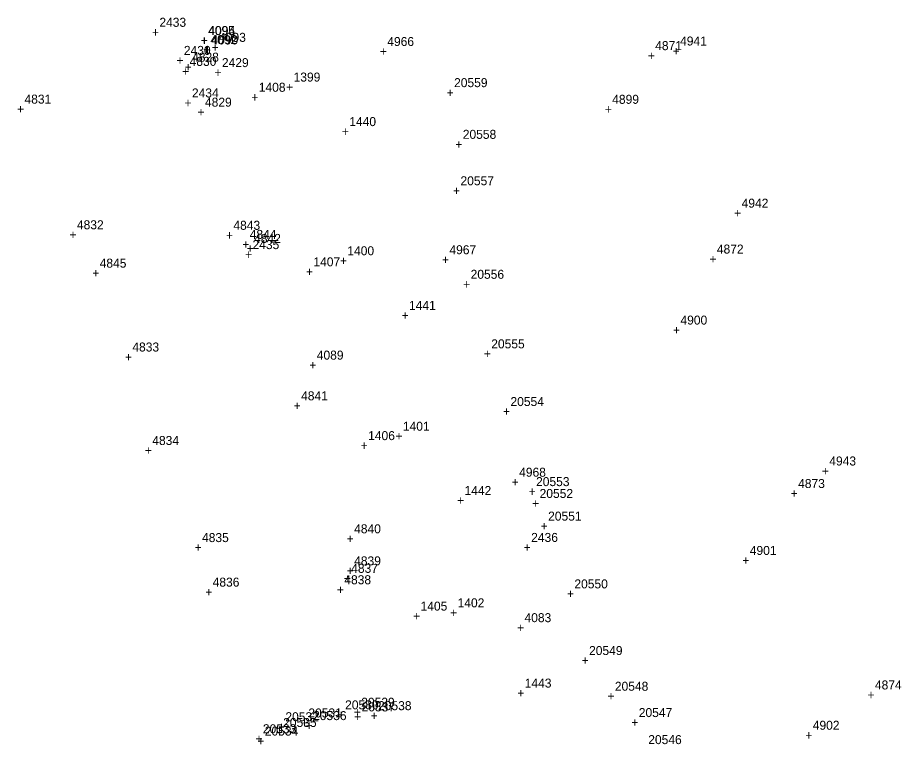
# Model space of a CAD drawing. Extents: x 1036751 to 1042192, y 772604 to 785439.
# Drawn here: x 1038276.6 to 1038522.1, y 779180.8 to 779382.7 of the extents above; entities that cross this region are included whole.
import ezdxf

# ---------------------------------------------------------------- set-up
doc = ezdxf.new("R2010")
doc.units = 0
for name, color, linetype in [('S_Drainage_Ditch_Line', 7, 'Continuous'), ('S_Ground_Elevation', 7, 'Continuous'), ('S_Misc_MiscFeature', 7, 'Continuous'), ('S_Property_IronPipeFound', 7, 'Continuous'), ('S_Property_Mailbox', 7, 'Continuous'), ('S_Property_StoneWall', 7, 'Continuous'), ('S_Roadway_Centerline', 7, 'Continuous'), ('S_Roadway_Edge_Pavement', 7, 'Continuous'), ('S_Trees_Conifer_Pay', 7, 'Continuous'), ('S_Utilities_Pole_Power', 7, 'Continuous'), ('S_Utilities_UG_Water_Gate', 7, 'Continuous'), ('S_Utilities_UG_Water_Line', 7, 'Continuous')]:
    doc.layers.add(name, color=color, linetype=linetype)

msp = doc.modelspace()

# ---------------------------------------------------------------- texts
at = {"layer": 'S_Drainage_Ditch_Line'}
for s, p in [('4871', (1038453.71, 779373.65)), ('+', (1038451.65, 779370.9)), ('4872', (1038470.85, 779317.13)), ('+', (1038468.79, 779314.38)), ('4873', (1038493.43, 779251.98)), ('+', (1038491.37, 779249.23)), ('4874', (1038514.77, 779196.01)), ('+', (1038512.71, 779193.26))]:
    msp.add_text(s, height=2.5, dxfattribs=at).set_placement(p)
at = {"layer": 'S_Ground_Elevation'}
for s, p in [('4966', (1038379.27, 779374.8)), ('4941', (1038460.63, 779374.94)), ('+', (1038377.21, 779372.05)), ('+', (1038458.56, 779372.19)), ('4828', (1038325.04, 779370.45)), ('+', (1038322.97, 779367.7)), ('4899', (1038441.77, 779358.74)), ('4829', (1038328.61, 779357.94)), ('+', (1038326.55, 779355.19)), ('+', (1038439.71, 779355.99)), ('4942', (1038477.73, 779329.88)), ('+', (1038475.67, 779327.13)), ('4832', (1038293.03, 779323.88)), ('4843', (1038336.51, 779323.73)), ('+', (1038290.97, 779321.13)), ('+', (1038334.45, 779320.98)), ('4842', (1038342.27, 779320.08)), ('+', (1038340.21, 779317.33)), ('4967', (1038396.54, 779316.94)), ('+', (1038394.48, 779314.19)), ('4900', (1038460.74, 779297.39)), ('+', (1038458.67, 779294.64)), ('4833', (1038308.43, 779289.91)), ('+', (1038306.37, 779287.16)), ('4841', (1038355.32, 779276.35)), ('+', (1038353.26, 779273.6)), ('4834', (1038313.97, 779263.94)), ('+', (1038311.91, 779261.19)), ('4943', (1038502.09, 779258.24)), ('4968', (1038415.91, 779255.12)), ('+', (1038500.03, 779255.49)), ('+', (1038413.85, 779252.37)), ('4840', (1038370.06, 779239.4)), ('4835', (1038327.79, 779236.96)), ('+', (1038367.99, 779236.65)), ('+', (1038325.73, 779234.21)), ('4901', (1038480, 779233.38)), ('4839', (1038370.06, 779230.49)), ('+', (1038477.94, 779230.63)), ('+', (1038368, 779227.74)), ('4838', (1038367.33, 779225.24)), ('+', (1038365.27, 779222.49)), ('20537', (1038372.13, 779189.91)), ('20538', (1038376.71, 779190.25)), ('20536', (1038358.66, 779187.49)), ('+', (1038370.07, 779187.16)), ('+', (1038374.65, 779187.5)), ('20535', (1038350.34, 779185.58)), ('+', (1038356.6, 779184.74)), ('4902', (1038497.5, 779184.81)), ('20534', (1038345.23, 779183.19)), ('+', (1038348.28, 779182.83)), ('+', (1038495.44, 779182.06)), ('+', (1038343.17, 779180.44))]:
    msp.add_text(s, height=2.5, dxfattribs=at).set_placement(p)
at = {"layer": 'S_Misc_MiscFeature'}
for s, p in [('20559', (1038397.83, 779363.37)), ('+', (1038395.77, 779360.62)), ('20558', (1038400.25, 779349.01)), ('+', (1038398.19, 779346.26)), ('20557', (1038399.61, 779336.1)), ('+', (1038397.55, 779333.35)), ('20556', (1038402.43, 779310.12)), ('+', (1038400.36, 779307.37)), ('20555', (1038408.16, 779290.79)), ('+', (1038406.1, 779288.04)), ('20554', (1038413.5, 779274.76)), ('+', (1038411.44, 779272.01)), ('20553', (1038420.61, 779252.51)), ('+', (1038418.55, 779249.76)), ('20552', (1038421.6, 779249.22)), ('+', (1038419.54, 779246.47)), ('20551', (1038423.96, 779242.92)), ('+', (1038421.9, 779240.17)), ('20550', (1038431.26, 779224.09)), ('+', (1038429.2, 779221.34)), ('20549', (1038435.34, 779205.57)), ('+', (1038433.28, 779202.82)), ('20548', (1038442.51, 779195.65)), ('+', (1038440.45, 779192.9)), ('20547', (1038449.16, 779188.34)), ('+', (1038447.09, 779185.59)), ('20546', (1038451.79, 779180.82))]:
    msp.add_text(s, height=2.5, dxfattribs=at).set_placement(p)
at = {"layer": 'S_Property_IronPipeFound'}
for s, p in [('2430', (1038322.75, 779372.33)), ('+', (1038320.69, 779369.58))]:
    msp.add_text(s, height=2.5, dxfattribs=at).set_placement(p)
at = {"layer": 'S_Property_Mailbox'}
for s, p in [('2429', (1038333.32, 779368.94)), ('+', (1038331.26, 779366.19))]:
    msp.add_text(s, height=2.5, dxfattribs=at).set_placement(p)
at = {"layer": 'S_Property_StoneWall'}
for s, p in [('4830', (1038324.34, 779369.28)), ('+', (1038322.28, 779366.53)), ('4831', (1038278.46, 779358.79)), ('+', (1038276.4, 779356.04)), ('4844', (1038341.04, 779321.2)), ('+', (1038338.98, 779318.45)), ('4845', (1038299.35, 779313.21)), ('+', (1038297.29, 779310.46)), ('4837', (1038369.24, 779228.41)), ('4836', (1038330.75, 779224.58)), ('+', (1038367.18, 779225.66)), ('+', (1038328.69, 779221.83)), ('20530', (1038367.55, 779190.48)), ('20529', (1038372.03, 779191.21)), ('20532', (1038350.95, 779187.18)), ('20531', (1038357.33, 779188.23)), ('+', (1038365.49, 779187.73)), ('+', (1038369.97, 779188.46)), ('+', (1038355.27, 779185.48)), ('20533', (1038344.7, 779183.84)), ('+', (1038348.89, 779184.43)), ('+', (1038342.64, 779181.09))]:
    msp.add_text(s, height=2.5, dxfattribs=at).set_placement(p)
at = {"layer": 'S_Roadway_Centerline'}
for s, p in [('1399', (1038353.24, 779364.92)), ('+', (1038351.18, 779362.17)), ('1400', (1038368.17, 779316.66)), ('+', (1038366.11, 779313.91)), ('1401', (1038383.6, 779267.9)), ('+', (1038381.54, 779265.15)), ('1402', (1038398.81, 779218.83)), ('+', (1038396.75, 779216.08))]:
    msp.add_text(s, height=2.5, dxfattribs=at).set_placement(p)
at = {"layer": 'S_Roadway_Edge_Pavement'}
for s, p in [('1408', (1038343.56, 779362.09)), ('+', (1038341.5, 779359.34)), ('1440', (1038368.71, 779352.55)), ('+', (1038366.65, 779349.8)), ('1407', (1038358.74, 779313.58)), ('+', (1038356.67, 779310.83)), ('1441', (1038385.31, 779301.48)), ('+', (1038383.25, 779298.73)), ('1406', (1038373.95, 779265.29)), ('+', (1038371.89, 779262.54)), ('1442', (1038400.73, 779250.03)), ('+', (1038398.67, 779247.28)), ('1405', (1038388.52, 779217.92)), ('+', (1038386.46, 779215.17)), ('1443', (1038417.46, 779196.52)), ('+', (1038415.4, 779193.77))]:
    msp.add_text(s, height=2.5, dxfattribs=at).set_placement(p)
at = {"layer": 'S_Trees_Conifer_Pay'}
for s, p in [('2433', (1038315.94, 779380.14)), ('+', (1038313.88, 779377.39)), ('2434', (1038324.99, 779360.51)), ('+', (1038322.93, 779357.76)), ('2435', (1038341.82, 779318.37)), ('+', (1038339.76, 779315.62))]:
    msp.add_text(s, height=2.5, dxfattribs=at).set_placement(p)
at = {"layer": 'S_Utilities_Pole_Power'}
for s, p in [('2436', (1038419.25, 779237)), ('+', (1038417.18, 779234.25))]:
    msp.add_text(s, height=2.5, dxfattribs=at).set_placement(p)
at = {"layer": 'S_Utilities_UG_Water_Gate'}
for s, p in [('4094', (1038329.56, 779377.83)), ('4093', (1038332.54, 779375.96)), ('+', (1038327.5, 779375.08)), ('+', (1038330.48, 779373.21))]:
    msp.add_text(s, height=2.5, dxfattribs=at).set_placement(p)
at = {"layer": 'S_Utilities_UG_Water_Line'}
for s, p in [('4095', (1038329.47, 779377.85)), ('+', (1038327.41, 779375.1)), ('4092', (1038330.14, 779375.33)), ('4090', (1038330.38, 779375.23)), ('+', (1038328.08, 779372.58)), ('+', (1038328.32, 779372.48)), ('4089', (1038359.68, 779287.66)), ('+', (1038357.62, 779284.91)), ('4083', (1038417.4, 779214.7)), ('+', (1038415.34, 779211.95))]:
    msp.add_text(s, height=2.5, dxfattribs=at).set_placement(p)

doc.saveas('drawing.dxf')
